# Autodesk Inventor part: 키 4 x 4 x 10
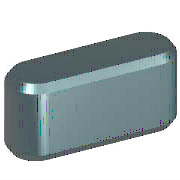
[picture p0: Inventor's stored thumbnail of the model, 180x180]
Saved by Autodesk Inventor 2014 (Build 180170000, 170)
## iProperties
IsCustomPart: 1
Created: 2012-02
Part Number: 키 4 x 4 x 10
Material: 강철, 연강
Description: 키 및 해당 키홈
Document SubType Name: Modeling
Standard: KS B 1311
Designer: test
Standards Organization: KS
Language: ko-KR
Size Designation: 4 x 4 x 10
Categories: <MemberInstance><Categories><Category DisplayName="샤프트 부품" InternalName="7f7aeb1f-a693-4053-b835-cee3144e0d98" Mnemonic="SHFT"><Category DisplayName="키" Interna
Density: 1 g/cm^3
Appearance: Steel
Author: test
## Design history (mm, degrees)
sketch "스케치1"
  geometry: L1 (2, 2)-(8, 2); L2 (8, -2)-(2, -2); L3 (0, 9.4)-(0, -7.4) reference; L4 (-5, 0)-(30, 0) reference; L5 (10, 0)-(10, 7); A1 r 2 centre (2, 0) between (2, 2) and (2, -2); A2 r 2 centre (8, 0) between (8, -2) and (8, 2)
  constraints: 6 end point, 5 point on circle, 4 tangent, 3 point on line, 2 centre point, 1 horizontal, 1 parallel, 1 perpendicular
  dimensions: "d0" = 2 radius of A1 (= 0.5 x PB); "d13" = 2 radius of A2 (= 0.5 x PB); "d14" = 10 distance between parallel lines of L5 L3 (= NLG)
extrude "본체1" new body sketch "스케치1" taper "d3" = 0 deg; stored distance "d4" = 10
workplane "Work Plane3"
body "Solid1"
workplane "Work Plane1"
workplane "Work Plane2"
chamfer "모따기1" distance "d8" = 0.25 (= PHH); stored, may be unused: second distance "d9" = 0.25 (= PHH), angle "d15" = 45 deg
other parameters: "d1" = -2.5 (= -PNT), "d2" = 1.5 (= PH - PNT), "NLG" = 10 [user parameter; used in 3 equation terms], "PB" = 4 [user parameter; used in 2 equation terms], "PNT" = 2.5 [user parameter; used in 2 equation terms], "PH" = 4 [user parameter; used in 1 equation term], "PHH" = 0.25 [user parameter; used in 2 equation terms], "d10" = 0, "d16" = 0, "d17" = 0, "d18" = 0, "WDMAX" = 12 [user parameter], "RR" = 0.08 [user parameter], "PUEB" = 1.8 [user parameter]
